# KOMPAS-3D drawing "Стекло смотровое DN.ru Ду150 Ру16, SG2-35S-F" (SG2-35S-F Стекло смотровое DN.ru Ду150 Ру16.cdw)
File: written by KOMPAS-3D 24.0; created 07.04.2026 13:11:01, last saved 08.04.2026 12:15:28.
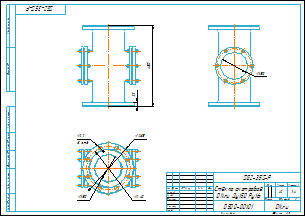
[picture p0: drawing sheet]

Document properties: Автор: Main; Форматы листов документа: A4; Полное имя файла: SG2-35S-FСтекло смотровое DN.ru Ду150 Ру16 (3d).cdw; Масса: 42; Наименование: Стекло смотровое DN.ru Ду150 Ру16; Количество листов документа: 1; Примечание: D500-00101

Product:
- Body: Тело 1  | qty 1
    Масса: 46.781742
- Part/product: Стекло смотровое DN.ru Ду150 Ру16  | designation SG2-35S-F
    Масса: 42
    Раздел спецификации: Прочие изделия
    Форматы листов документа: A4
    Примечание: D500-00101

Views: Вид 1, Снизу, Проекционный вид 2
Referenced files in D:\DN.ru Аутсерс\Стекло смотровое DN.ru\Стекло смотровое DN.ru SG2-34G-F тип В ГОСТ 21836-2021 Ду100 Ру16, углеродистая сталь, фланцевое\: SG2-34G-F тип В Стекло смотровое DN.ru Ду100 Ру16.m3d, SG2-34G-F тип ВСтекло смотровое DN.ru Ду100 Ру16.cdw
Referenced files in D:\DN.ru Аутсерс\Стекло смотровое DN.ru\SG2-35S-F Стекло смотровое DN.ru Ду150 Ру16\: SG2-35S-F Стекло смотровое DN.ru Ду150 Ру16.m3d
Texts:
  SG2-35S-F
  Стекло смотровое
  DN.ru Ду150 Ру16
  Стекло смотровое DN.ru Ду150 Ру16
  SG2-35S-F Стекло смотровое DN.ru Ду150 Ру16
Dimensions and other numbers on the sheet: 0; 3; 2; 4; 450; 22; 285; 240; 150; 8 отв.; 1:4; 1; 42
